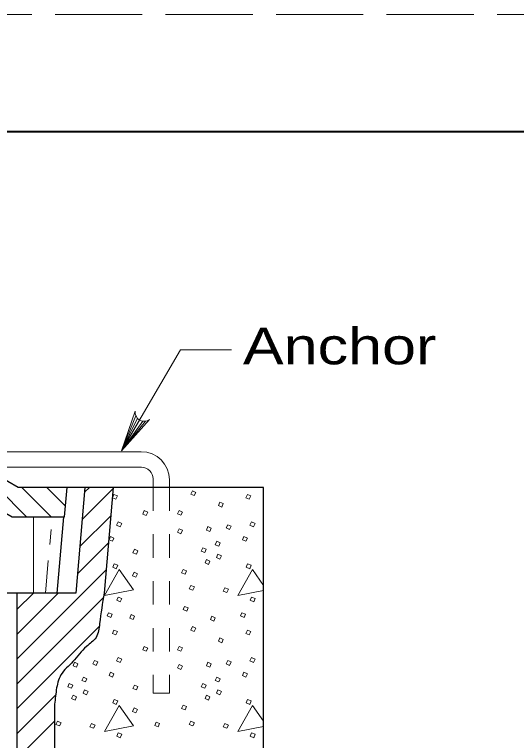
# Model space of a CAD drawing. Extents: x 1036.7 to 1070.7, y 883.9 to 905.9.
# Drawn here: x 1048.888 to 1051.032, y 902.809 to 905.908 of the extents above; entities that cross this region are included whole.
import ezdxf

# ---------------------------------------------------------------- set-up
doc = ezdxf.new("R2010")
doc.units = 0
doc.header["$LTSCALE"] = 0.062
doc.linetypes.add('LONG_DASHED', pattern=[7.5, 6, -1.5])
doc.linetypes.add('SHORT_DASHED', pattern=[2.7, 1.5, -1.2])
doc.layers.add('1', color=7, linetype='Continuous', lineweight=13)

msp = doc.modelspace()

# ---------------------------------------------------------------- linework, layer by layer
at = {"layer": '1', "lineweight": 25}
for p, q in [((1038.67333, 905.40825), (1070.17333, 905.40825)), ((1048.90392, 903.88892), (1047.83108, 904.5075)), ((1049.30917, 903.88892), (1048.90392, 903.88892)), ((1049.1015, 903.76383), (1049.11233, 903.88892)), ((1049.95158, 900.58467), (1049.95158, 903.88892)), ((1049.09683, 903.76383), (1049.06858, 903.43767)), ((1048.89925, 903.43767), (1046.7915, 903.43767)), ((1048.93683, 903.43767), (1046.7915, 903.43767)), ((1048.89817, 903.43767), (1048.89817, 900.59067)), ((1049.05833, 902.95508), (1049.05833, 900.58333))]:
    msp.add_line(p, q, dxfattribs=at)
at = {"layer": '1'}
for p, q in [((1049.40617, 904.19442), (1049.34458, 904.04483)), ((1049.413, 904.18417), (1049.34458, 904.04483)), ((1049.422, 904.177), (1049.34458, 904.04483)), ((1049.44792, 904.17225), (1049.34458, 904.04483)), ((1049.43583, 904.17217), (1049.34458, 904.04483)), ((1048.63925, 904.04158), (1049.42942, 904.04158)), ((1048.69008, 904.01225), (1048.9385, 903.76383)), ((1048.75433, 903.97517), (1049.42983, 903.97517)), ((1049.47983, 903.92517), (1049.47983, 903.88892)), ((1049.54942, 903.92158), (1049.54942, 903.88892)), ((1048.91942, 903.88892), (1049.04458, 903.76383)), ((1049.0255, 903.88892), (1049.10542, 903.80892)), ((1049.18708, 903.86842), (1049.20758, 903.88892)), ((1049.177, 903.75242), (1049.30875, 903.88417)), ((1049.16692, 903.63625), (1049.29867, 903.76808)), ((1048.96875, 903.76383), (1048.96875, 903.43767)), ((1049.04367, 903.70933), (1049.03808, 903.64492)), ((1049.15692, 903.52025), (1049.28867, 903.652)), ((1049.03225, 903.57725), (1049.02017, 903.43767)), ((1048.89817, 903.15558), (1049.27858, 903.53592)), ((1049.95158, 903.471), (1049.9045, 903.53817)), ((1048.89817, 903.36758), (1048.96825, 903.43767)), ((1048.89817, 903.26158), (1049.07425, 903.43767)), ((1048.89817, 903.0495), (1049.26733, 903.41875)), ((1048.89817, 902.94358), (1049.24967, 903.29508)), ((1048.89817, 902.83758), (1049.06392, 903.00333)), ((1049.95158, 902.89133), (1049.9045, 902.9585)), ((1048.89817, 902.73158), (1049.05833, 902.89175))]:
    msp.add_line(p, q, dxfattribs=at)
at = {"layer": '1', "linetype": 'SHORT_DASHED'}
for p, q in [((1049.47983, 903.88892), (1049.47983, 903.01058)), ((1049.54942, 903.88892), (1049.54983, 903.01058)), ((1049.47983, 903.01058), (1049.54983, 903.01058))]:
    msp.add_line(p, q, dxfattribs=at)
at = {"layer": '1', "linetype": 'LONG_DASHED'}
msp.add_lwpolyline([(1036.67333, 883.90825), (1070.67333, 883.90825), (1070.67333, 905.90825), (1036.67333, 905.90825)], close=True, dxfattribs=at)
at = {"layer": '1', "lineweight": 40}
msp.add_lwpolyline([(1038.67333, 905.40825), (1070.17333, 905.40825), (1070.17333, 884.40825), (1038.67333, 884.40825)], close=True, dxfattribs=at)
msp.add_lwpolyline([(1038.67333, 905.40825), (1070.17333, 905.40825), (1070.17333, 884.40825), (1038.67333, 884.40825)], close=True, dxfattribs=at)
at = {"layer": '1'}
for points in [[(1049.34458, 904.04483), (1049.59758, 904.47608), (1049.81525, 904.47608)], [(1049.46458, 904.17967), (1049.34458, 904.04483), (1049.4035, 904.21542)], [(1049.9045, 903.53817), (1049.8425, 903.42725), (1049.95158, 903.44858)], [(1049.95158, 903.3305), (1049.94942, 903.33133), (1049.95158, 903.33675)], [(1049.9045, 902.9585), (1049.8425, 902.84758), (1049.95158, 902.86892)]]:
    msp.add_lwpolyline(points, dxfattribs=at)
at = {"layer": '1', "lineweight": 25}
for points in [[(1047.83925, 904.36233), (1048.87742, 903.76383), (1049.10158, 903.76383)], [(1049.18883, 903.88892), (1049.14975, 903.43767), (1048.89925, 903.43767)], [(1049.95158, 903.88892), (1049.30917, 903.88892), (1049.27008, 903.43767)]]:
    msp.add_lwpolyline(points, dxfattribs=at)
at = {"layer": '1'}
for points in [[(1049.31275, 903.859), (1049.32775, 903.853), (1049.32075, 903.839), (1049.30575, 903.845)], [(1049.64758, 903.875), (1049.66258, 903.868), (1049.65558, 903.854), (1049.64058, 903.86)], [(1049.8825, 903.859), (1049.8975, 903.853), (1049.8905, 903.839), (1049.8755, 903.845)], [(1049.7645, 903.826), (1049.7795, 903.82), (1049.7735, 903.805), (1049.75858, 903.812)], [(1049.44167, 903.79), (1049.45667, 903.783), (1049.45067, 903.76908), (1049.43567, 903.775)], [(1049.59067, 903.79), (1049.60558, 903.784), (1049.59858, 903.77008), (1049.58367, 903.776)], [(1049.33075, 903.74208), (1049.34575, 903.73508), (1049.33875, 903.72108), (1049.32375, 903.72808)], [(1049.9005, 903.74208), (1049.9155, 903.73508), (1049.9085, 903.72108), (1049.8935, 903.72808)], [(1049.59067, 903.71208), (1049.60558, 903.70608), (1049.59858, 903.69108), (1049.58367, 903.69808)], [(1049.71358, 903.72208), (1049.72858, 903.71508), (1049.72258, 903.70108), (1049.70758, 903.70708)], [(1049.7985, 903.73008), (1049.8135, 903.72408), (1049.8065, 903.70908), (1049.7915, 903.71608)], [(1049.29775, 903.68008), (1049.31275, 903.67308), (1049.30675, 903.65908), (1049.29175, 903.66608)], [(1049.8675, 903.68008), (1049.8825, 903.67308), (1049.8765, 903.65908), (1049.8615, 903.66608)], [(1049.75158, 903.65908), (1049.76658, 903.65208), (1049.76058, 903.63808), (1049.74558, 903.64408)], [(1049.39975, 903.62517), (1049.41467, 903.61817), (1049.40875, 903.60417), (1049.39375, 903.61017)], [(1049.69158, 903.63108), (1049.70658, 903.62517), (1049.70058, 903.61117), (1049.68558, 903.61717)], [(1049.70758, 903.58117), (1049.72258, 903.57417), (1049.71658, 903.56017), (1049.70158, 903.56717)], [(1049.75658, 903.60417), (1049.7715, 903.59717), (1049.76558, 903.58317), (1049.75058, 903.59017)], [(1049.31375, 903.56317), (1049.32875, 903.55717), (1049.32275, 903.54217), (1049.30775, 903.54917)], [(1049.8835, 903.56317), (1049.8985, 903.55717), (1049.8925, 903.54217), (1049.8775, 903.54917)], [(1049.33475, 903.53817), (1049.27275, 903.42725), (1049.39575, 903.45125)], [(1049.39875, 903.52717), (1049.41367, 903.52017), (1049.40675, 903.50617), (1049.39175, 903.51217)], [(1049.60758, 903.53917), (1049.62258, 903.53317), (1049.61658, 903.51917), (1049.60158, 903.52517)], [(1049.64158, 903.47025), (1049.65658, 903.46425), (1049.64958, 903.45025), (1049.63458, 903.45625)], [(1049.7865, 903.46025), (1049.8015, 903.45425), (1049.7945, 903.44025), (1049.7795, 903.44625)], [(1049.33075, 903.42125), (1049.34575, 903.41525), (1049.33975, 903.40025), (1049.32475, 903.40725)], [(1049.9005, 903.42125), (1049.9155, 903.41525), (1049.9095, 903.40025), (1049.8945, 903.40725)], [(1049.61458, 903.38125), (1049.62958, 903.37525), (1049.62358, 903.36125), (1049.60858, 903.36725)], [(1049.28975, 903.35425), (1049.30475, 903.34825), (1049.29875, 903.33333), (1049.28375, 903.34025)], [(1049.38575, 903.34625), (1049.40075, 903.33925), (1049.39475, 903.32533), (1049.37975, 903.33133)], [(1049.73058, 903.33925), (1049.74558, 903.33233), (1049.73958, 903.31833), (1049.72458, 903.32533)], [(1049.8595, 903.35425), (1049.8745, 903.34825), (1049.8685, 903.33333), (1049.8535, 903.34025)], [(1049.31275, 903.27933), (1049.32775, 903.27333), (1049.32075, 903.25933), (1049.30575, 903.26533)], [(1049.64758, 903.29533), (1049.66258, 903.28833), (1049.65558, 903.27433), (1049.64058, 903.28033)], [(1049.8825, 903.27933), (1049.8975, 903.27333), (1049.8905, 903.25933), (1049.8755, 903.26533)], [(1049.7645, 903.24633), (1049.7795, 903.24033), (1049.7735, 903.22533), (1049.75858, 903.23233)], [(1049.44167, 903.21033), (1049.45667, 903.20333), (1049.45067, 903.18942), (1049.43567, 903.19533)], [(1049.59067, 903.21033), (1049.60558, 903.20433), (1049.59858, 903.19042), (1049.58367, 903.19633)], [(1049.22883, 903.15042), (1049.24375, 903.14442), (1049.23675, 903.12942), (1049.22183, 903.13642)], [(1049.33075, 903.16242), (1049.34575, 903.15542), (1049.33875, 903.14142), (1049.32375, 903.14842)], [(1049.7985, 903.15042), (1049.8135, 903.14442), (1049.8065, 903.12942), (1049.7915, 903.13642)], [(1049.9005, 903.16242), (1049.9155, 903.15542), (1049.9085, 903.14142), (1049.8935, 903.14842)], [(1049.14383, 903.14242), (1049.15883, 903.13542), (1049.15283, 903.12142), (1049.13783, 903.12742)], [(1049.59067, 903.13242), (1049.60558, 903.12642), (1049.59858, 903.11142), (1049.58367, 903.11842)], [(1049.71358, 903.14242), (1049.72858, 903.13542), (1049.72258, 903.12142), (1049.70758, 903.12742)], [(1049.29775, 903.10042), (1049.31275, 903.09342), (1049.30675, 903.07942), (1049.29175, 903.08642)], [(1049.8675, 903.10042), (1049.8825, 903.09342), (1049.8765, 903.07942), (1049.8615, 903.08642)], [(1049.12183, 903.05142), (1049.13683, 903.0455), (1049.13083, 903.0315), (1049.11583, 903.0375)], [(1049.18183, 903.07942), (1049.19683, 903.07242), (1049.19083, 903.05842), (1049.17583, 903.06442)], [(1049.69158, 903.05142), (1049.70658, 903.0455), (1049.70058, 903.0315), (1049.68558, 903.0375)], [(1049.75158, 903.07942), (1049.76658, 903.07242), (1049.76058, 903.05842), (1049.74558, 903.06442)], [(1049.18683, 903.0245), (1049.20183, 903.0175), (1049.19583, 903.0035), (1049.18083, 903.0105)], [(1049.39975, 903.0455), (1049.41467, 903.0385), (1049.40875, 903.0245), (1049.39375, 903.0305)], [(1049.75658, 903.0245), (1049.7715, 903.0175), (1049.76558, 903.0035), (1049.75058, 903.0105)], [(1049.13783, 903.0015), (1049.15283, 902.9945), (1049.14683, 902.9805), (1049.13183, 902.9875)], [(1049.70758, 903.0015), (1049.72258, 902.9945), (1049.71658, 902.9805), (1049.70158, 902.9875)], [(1049.33475, 902.9585), (1049.27275, 902.84758), (1049.39575, 902.87158)], [(1049.31375, 902.9835), (1049.32875, 902.9775), (1049.32275, 902.9625), (1049.30775, 902.9695)], [(1049.60758, 902.9595), (1049.62258, 902.9535), (1049.61658, 902.9395), (1049.60158, 902.9455)], [(1049.8835, 902.9835), (1049.8985, 902.9775), (1049.8925, 902.9625), (1049.8775, 902.9695)], [(1049.39875, 902.9475), (1049.41367, 902.9405), (1049.40675, 902.9265), (1049.39175, 902.9325)], [(1049.07183, 902.89058), (1049.08683, 902.88458), (1049.07983, 902.87058), (1049.06483, 902.87658)], [(1049.21683, 902.88058), (1049.23183, 902.87458), (1049.22483, 902.86058), (1049.20983, 902.86658)], [(1049.49267, 902.88658), (1049.50767, 902.88058), (1049.50167, 902.86658), (1049.48667, 902.87258)], [(1049.64158, 902.89058), (1049.65658, 902.88458), (1049.64958, 902.87058), (1049.63458, 902.87658)], [(1049.7865, 902.88058), (1049.8015, 902.87458), (1049.7945, 902.86058), (1049.7795, 902.86658)], [(1049.33075, 902.84158), (1049.34575, 902.83558), (1049.33975, 902.82058), (1049.32475, 902.82758)], [(1049.9005, 902.84158), (1049.9155, 902.83558), (1049.9095, 902.82058), (1049.8945, 902.82758)]]:
    msp.add_lwpolyline(points, close=True, dxfattribs=at)
for centre, radius, start, end in [((1050.65288, 903.65968), 0.78667, 180, 180), ((1049.44121, 904.20992), 0.0382, 171.7372, 307.56332)]:
    msp.add_arc(centre, radius, start, end, dxfattribs=at)
for centre, major_axis in [((1049.42945, 903.92162), (0.11994, 0)), ((1049.42987, 903.9252), (0.04998, 0))]:
    msp.add_ellipse(centre, major_axis=major_axis, ratio=0.999895, start_param=6.2831853, end_param=7.8539816, dxfattribs=at)
at = {"layer": '1', "lineweight": 25}
msp.add_spline([(1049.27008, 903.43767), (1049.25142, 903.30758), (1049.23608, 903.24875), (1049.19517, 903.21017), (1049.13733, 903.14567), (1049.08625, 903.08867), (1049.06642, 903.0245), (1049.05833, 902.95508)], degree=3, dxfattribs=at)

# ---------------------------------------------------------------- texts
at = {"layer": '1', "width": 1.25}
msp.add_text('Anchor', height=0.156, dxfattribs=at).set_placement((1049.86358, 904.41467))

doc.saveas('drawing.dxf')
